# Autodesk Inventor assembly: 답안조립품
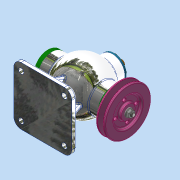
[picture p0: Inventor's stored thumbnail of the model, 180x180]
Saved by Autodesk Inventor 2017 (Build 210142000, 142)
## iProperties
Part Number: 답안조립품
Material: 일반
Document SubType Name: Assembly
Designer: MRC
Author: MRC
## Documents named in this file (16)
- C:\Users\MRC\Desktop\720811V1005\답안조립품.iam
- C:\Users\MRC\Desktop\720811V1005\본체.ipt
- C:\Users\MRC\Desktop\720811V1005\V-벨트풀리.ipt
- C:\Users\MRC\Desktop\720811V1005\너트 M8.ipt
- C:\Users\MRC\Desktop\720811V1005\뒤커버.ipt
- C:\Users\MRC\Desktop\720811V1005\베어링- 6202.ipt
- KS B 2023 - 6202 - 15 x 35 x 11 - 7.8.ipt
- C:\Users\MRC\Desktop\720811V1005\볼트 M4 x 12.ipt
- C:\Users\MRC\Desktop\720811V1005\볼트 M4 x 16.ipt
- C:\Users\MRC\Desktop\720811V1005\상부커버.ipt
- C:\Users\MRC\Desktop\720811V1005\슬라이드.ipt
- C:\Users\MRC\Desktop\720811V1005\앞커버.ipt
- C:\Users\MRC\Desktop\720811V1005\오일실 15 30 7.ipt
- C:\Users\MRC\Desktop\720811V1005\칼라.ipt
- C:\Users\MRC\Desktop\720811V1005\키 4 x 4 x 12.ipt
- C:\Users\MRC\Desktop\720811V1005\편심축.ipt
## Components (15 placed, 4 different names)
1. V-벨트풀리:1
2. KS B 2023 - 6202 - 15 x 35 x 11 - 7.8:1
3. KS B 2023 - 6202 - 15 x 35 x 11 - 7.8:2
4. KS B 1021 - 에 따름 ISO 1207 - 미터 A  M 4 x 12:1
5. KS B 1021 - 에 따름 ISO 1207 - 미터 A  M 4 x 12:2
6. KS B 1021 - 에 따름 ISO 1207 - 미터 A  M 4 x 12:3
7. KS B 1021 - 에 따름 ISO 1207 - 미터 A  M 4 x 12:4
8. ISO 4762 M4 x 16:2
9. ISO 4762 M4 x 16:1
10. ISO 4762 M4 x 16:3
11. ISO 4762 M4 x 16:4
12. ISO 4762 M4 x 16:5
13. ISO 4762 M4 x 16:6
14. ISO 4762 M4 x 16:7
15. ISO 4762 M4 x 16:8
